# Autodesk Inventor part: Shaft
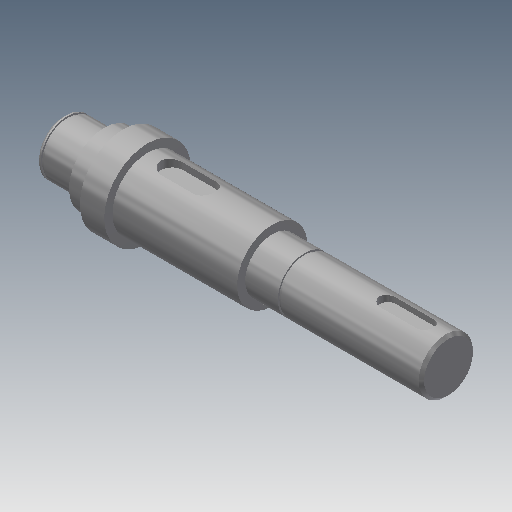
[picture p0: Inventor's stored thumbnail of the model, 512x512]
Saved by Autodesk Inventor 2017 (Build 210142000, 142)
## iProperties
Created: 2019-02
Part Number: Shaft
Material: Steel
Document SubType Name: Modeling
Designer: user
Density: 1 g/cm^3
Appearance: Steel
CustomPartVersion: 1
Author: user
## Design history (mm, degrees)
sketch "Main Sketch"
  geometry: L1 (0, 0)-(142, 0) reference; L2 (0, 0)-(0, 10); L3 (0, 10)-(15, 10); L4 (15, 10)-(15, 13); L5 (15, 13)-(22, 13); L6 (22, 13)-(22, 16); L7 (22, 16)-(31, 16); L8 (31, 16)-(31, 13); L9 (31, 13)-(61, 13); L10 (77, 13)-(77, 10); L11 (61, 13)-(77, 13); L12 (142, 10)-(142, 0); L13 (77, 10)-(142, 10)
  constraints: 26 end point, 6 vertical, 1 horizontal
  dimensions: "d3" = 20 diameter of L3 L1 (derived); "d4" = 26 diameter of L5 L1 (derived); "d5" = 32 diameter of L7 L1 (derived); "d6" = 26 diameter of L9 L1 (derived); "d7" = 26 diameter of L11 L1 (derived); "d8" = 20 diameter of L13 L1 (derived)
revolve "Revolution1" sketch "Main Sketch" stored, may be unused: angle "d9" = 0 deg
node "Keyway1"
node "Keyway2"
chamfer "Chamfer3" distance "d16" = 1; stored, may be unused: second distance "d17" = 0.125, angle "d18" = 45 deg
node "Retaining Ring Groove1"
chamfer "Chamfer2" distance "d13" = 1; stored, may be unused: second distance "d14" = 0.125, angle "d15" = 45 deg
node "Retaining Ring Groove2"
body "Solid1"
feature "iFeature27:1"
feature "iFeature27:2"
feature "iFeature3:1"
feature "iFeature3:2"
other parameters: "d0" = 0, "d1" = 0, "d2" = 0
